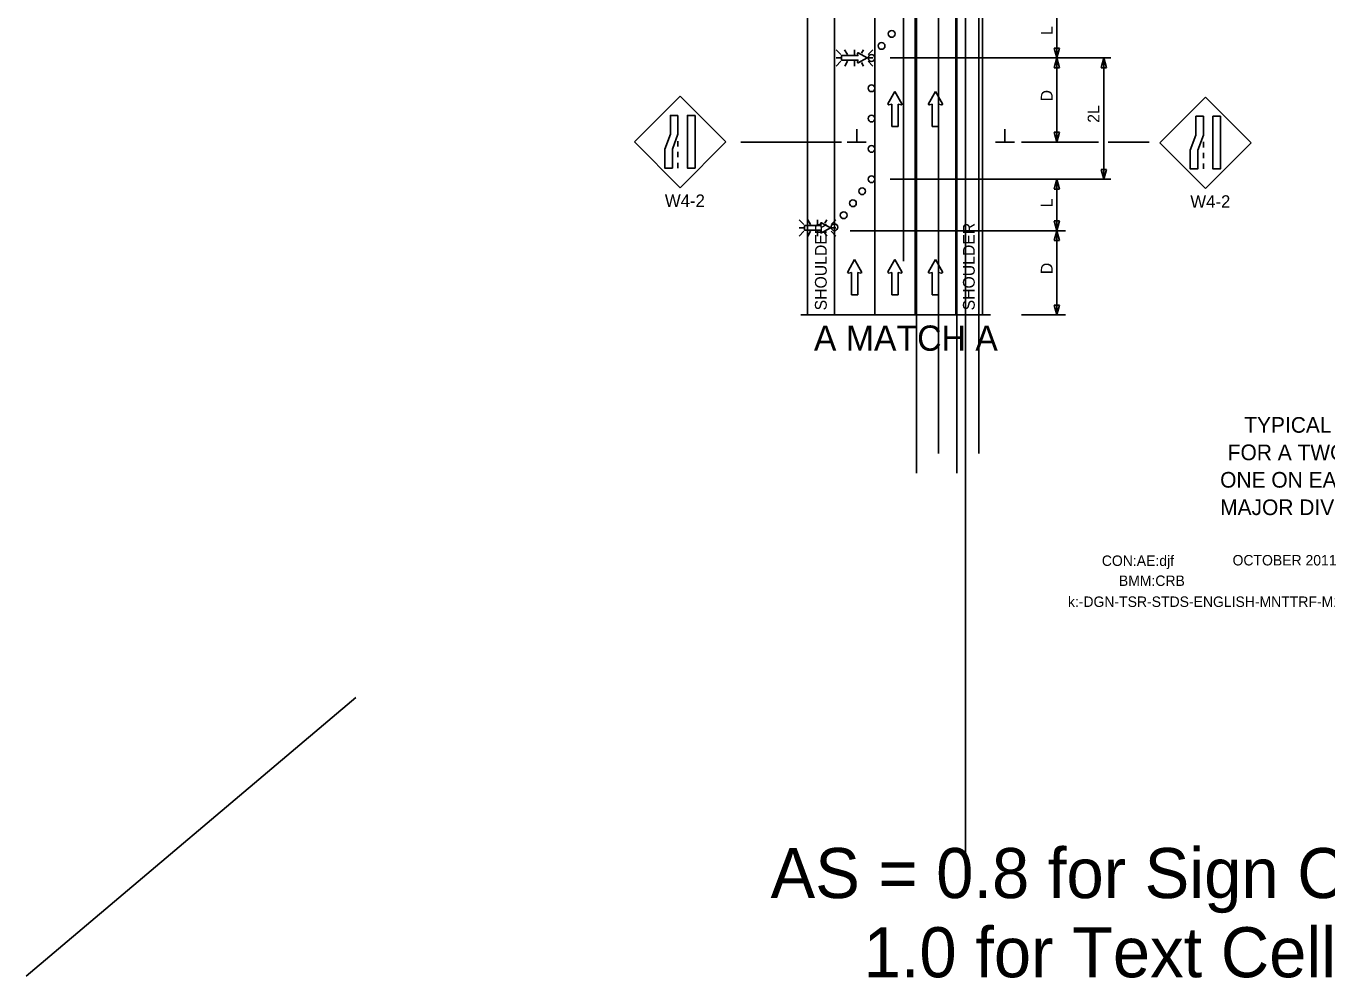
# Model space of a CAD drawing. Extents: x 16452 to 19508, y 5713 to 7079.
# Drawn here: x 16452 to 17224, y 5713 to 6279 of the extents above; entities that cross this region are included whole.
import ezdxf

# ---------------------------------------------------------------- set-up
doc = ezdxf.new("R2010")
doc.units = 0
for name, color, linetype in [('ALI_LEGAL_EX', 7, 'Continuous'), ('BORDER', 7, 'Continuous'), ('BORDER_SIGNAL_WO', 7, 'Continuous'), ('MT_SCRATCH_LEVEL_E', 7, 'Continuous'), ('PAVT_EDGE_EX', 7, 'Continuous'), ('TRAFFIC_SIGNS_PR', 7, 'Continuous'), ('TYPICAL_TEXT_DIMEN_PR', 7, 'Continuous')]:
    doc.layers.add(name, color=color, linetype=linetype)

msp = doc.modelspace()

# ---------------------------------------------------------------- linework, layer by layer
at = {"layer": 'ALI_LEGAL_EX'}
for p, q in [((16980.68, 6974.12), (16980.68, 6155.98)), ((17004.68, 6974.12), (17004.68, 6155.98)), ((16980.68, 6877.04), (16980.68, 6013.12)), ((17004.68, 6877.04), (17004.68, 6013.12)), ((16973.01, 6139.03), (16973.01, 6639.38)), ((16993.65, 6024.8), (16993.65, 6525.15)), ((17017.65, 6024.8), (17017.65, 6525.15)), ((16955.93, 6107.09), (16955.93, 6383.76)), ((16979.93, 6107.09), (16979.93, 6383.76)), ((17009.75, 5773.57), (17009.75, 6383.76))]:
    msp.add_line(p, q, dxfattribs=at)
for points in [[(16955.93, 6207.09), (16955.93, 6232.09)], [(16979.93, 6207.09), (16979.93, 6232.09)], [(16955.93, 6107.09), (16955.93, 6132.09)], [(16979.93, 6107.09), (16979.93, 6132.09)], [(16993.65, 6049.8), (16993.65, 6024.8)]]:
    msp.add_lwpolyline(points, dxfattribs=at)
at = {"layer": 'MT_SCRATCH_LEVEL_E'}
for p, q in [((16967.85, 6239.76), (16963.74, 6232.52)), ((16972, 6232.52), (16967.85, 6239.76)), ((16991.9, 6239.76), (16987.79, 6232.52)), ((16996.05, 6232.52), (16991.9, 6239.76)), ((16964.22, 6231.84), (16966, 6232.15)), ((16966, 6232.15), (16966, 6218.89)), ((16969.74, 6218.89), (16969.74, 6232.15)), ((16969.74, 6232.15), (16971.52, 6231.84)), ((16988.27, 6231.84), (16990.05, 6232.15)), ((16990.05, 6232.15), (16990.05, 6218.89)), ((16993.79, 6218.89), (16993.79, 6232.15)), ((16993.79, 6232.15), (16995.57, 6231.84)), ((16966, 6218.89), (16969.74, 6218.89)), ((16990.05, 6218.89), (16993.79, 6218.89)), ((16943.95, 6139.9), (16939.84, 6132.66)), ((16948.09, 6132.66), (16943.95, 6139.9)), ((16967.85, 6139.9), (16963.74, 6132.66)), ((16972, 6132.66), (16967.85, 6139.9)), ((16991.9, 6139.9), (16987.79, 6132.66)), ((16996.05, 6132.66), (16991.9, 6139.9)), ((16940.32, 6131.97), (16942.1, 6132.29)), ((16942.1, 6132.29), (16942.1, 6119.03)), ((16945.84, 6119.03), (16945.84, 6132.29)), ((16945.84, 6132.29), (16947.61, 6131.97)), ((16964.22, 6131.97), (16966, 6132.29)), ((16966, 6132.29), (16966, 6119.03)), ((16969.74, 6119.03), (16969.74, 6132.29)), ((16969.74, 6132.29), (16971.52, 6131.97)), ((16988.27, 6131.97), (16990.05, 6132.29)), ((16990.05, 6132.29), (16990.05, 6119.03)), ((16993.79, 6119.03), (16993.79, 6132.29)), ((16993.79, 6132.29), (16995.57, 6131.97)), ((16942.1, 6119.03), (16945.84, 6119.03)), ((16966, 6119.03), (16969.74, 6119.03)), ((16990.05, 6119.03), (16993.79, 6119.03))]:
    msp.add_line(p, q, dxfattribs=at)
for centre, start, end in [((16964.15, 6232.29), 150.42484, 279.96381), ((16971.59, 6232.29), 260.03619, 29.77312), ((16988.2, 6232.29), 150.42484, 279.96381), ((16995.64, 6232.29), 260.03619, 29.77312), ((16940.24, 6132.43), 150.42484, 279.96381), ((16947.68, 6132.43), 260.03619, 29.77312), ((16964.15, 6132.43), 150.42484, 279.96381), ((16971.59, 6132.43), 260.03619, 29.77312), ((16988.2, 6132.43), 150.42484, 279.96381), ((16995.64, 6132.43), 260.03619, 29.77312)]:
    msp.add_arc(centre, 0.463, start, end, dxfattribs=at)
at = {"layer": 'PAVT_EDGE_EX'}
for p, q in [((16915.93, 6383.76), (16915.93, 6107.09)), ((16931.93, 6383.76), (16931.93, 6107.09)), ((17003.93, 6383.76), (17003.93, 6107.09)), ((17019.93, 6383.76), (17019.93, 6107.09))]:
    msp.add_line(p, q, dxfattribs=at)
at = {"layer": 'TRAFFIC_SIGNS_PR'}
for p, q in [((16935.71, 6261.75), (16932.89, 6264.57)), ((16938, 6264.57), (16939.63, 6261.75)), ((16943.79, 6261.75), (16943.79, 6264.57)), ((16949.26, 6264.57), (16948.05, 6262.48)), ((16954.69, 6264.57), (16951.88, 6261.75)), ((16935.71, 6259.72), (16932.89, 6259.72)), ((16935.71, 6257.69), (16932.89, 6254.87)), ((16939.66, 6257.69), (16938.03, 6254.87)), ((16943.79, 6257.69), (16943.79, 6254.87)), ((16947.97, 6257.05), (16949.24, 6254.87)), ((16951.88, 6259.72), (16954.69, 6259.72)), ((16954.69, 6254.87), (16951.88, 6257.69)), ((16840.31, 6236.92), (16813.16, 6209.77)), ((16867.46, 6209.77), (16840.31, 6236.92)), ((17152.24, 6236.44), (17125.08, 6209.29)), ((17179.39, 6209.29), (17152.24, 6236.44)), ((16813.16, 6209.77), (16840.31, 6182.62)), ((16839.06, 6210.26), (16839.06, 6207.06)), ((16840.31, 6182.62), (16867.46, 6209.77)), ((17150.99, 6209.78), (17150.99, 6206.58)), ((16839.06, 6203.86), (16839.06, 6200.66)), ((17125.08, 6209.29), (17152.24, 6182.13)), ((17150.99, 6203.38), (17150.99, 6200.18)), ((17152.24, 6182.13), (17179.39, 6209.29)), ((16839.06, 6197.46), (16839.06, 6194.26)), ((17150.99, 6196.98), (17150.99, 6193.78)), ((16913.83, 6160.8), (16911.01, 6163.62)), ((16916.13, 6163.62), (16917.76, 6160.8)), ((16921.92, 6160.8), (16921.92, 6163.62)), ((16927.39, 6163.62), (16926.18, 6161.53)), ((16932.82, 6163.62), (16930, 6160.8)), ((16913.83, 6158.77), (16911.01, 6158.77)), ((16913.83, 6156.74), (16911.01, 6153.92)), ((16917.78, 6156.74), (16916.15, 6153.92)), ((16921.92, 6156.74), (16921.92, 6153.92)), ((16926.1, 6156.1), (16927.36, 6153.92)), ((16930, 6158.77), (16932.82, 6158.77)), ((16932.82, 6153.92), (16930, 6156.74))]:
    msp.add_line(p, q, dxfattribs=at)
for points in [[(16945.62, 6262.4), (16945.85, 6261.11), (16936.12, 6261.11), (16936.12, 6258.36), (16945.85, 6258.36), (16945.62, 6257.06)], [(16946.12, 6256.71), (16951.43, 6259.72), (16946.12, 6262.76)], [(16923.74, 6161.45), (16923.97, 6160.15), (16914.25, 6160.15), (16914.25, 6157.41), (16923.97, 6157.41), (16923.74, 6156.11)], [(16924.24, 6155.75), (16929.55, 6158.77), (16924.24, 6161.81)]]:
    msp.add_lwpolyline(points, dxfattribs=at)
for points in [[(16839.06, 6225.5), (16839.06, 6214.32), (16835.72, 6205.44), (16835.72, 6194.26), (16831.22, 6194.26), (16831.22, 6205.44), (16834.57, 6214.32), (16834.57, 6225.5)], [(16849.2, 6225.5), (16849.2, 6194.26), (16844.7, 6194.26), (16844.7, 6225.5)], [(17150.99, 6225.02), (17150.99, 6213.84), (17147.65, 6204.96), (17147.65, 6193.78), (17143.15, 6193.78), (17143.15, 6204.96), (17146.5, 6213.84), (17146.5, 6225.02)], [(17161.13, 6225.02), (17161.13, 6193.78), (17156.63, 6193.78), (17156.63, 6225.02)]]:
    msp.add_lwpolyline(points, close=True, dxfattribs=at)
for centre in [(16965.93, 6273.93), (16959.93, 6266.79), (16953.93, 6259.65), (16953.93, 6241.65), (16953.93, 6223.65), (16953.93, 6205.65), (16953.93, 6187.65), (16948.43, 6180.52), (16942.94, 6173.39), (16937.44, 6166.26), (16931.94, 6159.14)]:
    msp.add_circle(centre, 2, dxfattribs=at)
for centre, start, end in [((16945.95, 6262.46), 61.48329, 189.95933), ((16945.95, 6257.01), 170.73078, 298.89165), ((16924.08, 6161.51), 61.48329, 189.95933), ((16924.08, 6156.05), 170.73078, 298.89165)]:
    msp.add_arc(centre, 0.341, start, end, dxfattribs=at)
at = {"layer": 'TYPICAL_TEXT_DIMEN_PR'}
for p, q in [((17064.03, 6259.65), (17064.03, 6288.21)), ((17064.03, 6259.65), (17062.46, 6265.51)), ((17062.46, 6265.51), (17064.03, 6265.51)), ((17064.03, 6265.51), (17065.6, 6265.51)), ((17065.6, 6265.51), (17064.03, 6259.65)), ((17096.07, 6259.65), (16964.93, 6259.65)), ((17062.46, 6253.79), (17064.03, 6259.65)), ((17064.03, 6259.65), (17064.03, 6209.65)), ((17064.03, 6259.65), (17065.6, 6253.79)), ((17090.26, 6253.79), (17091.83, 6259.65)), ((17091.83, 6259.65), (17093.4, 6253.79)), ((17091.83, 6259.65), (17091.83, 6187.65)), ((17064.03, 6253.79), (17062.46, 6253.79)), ((17065.6, 6253.79), (17064.03, 6253.79)), ((17091.83, 6253.79), (17090.26, 6253.79)), ((17093.4, 6253.79), (17091.83, 6253.79)), ((16945.22, 6209.65), (16945.22, 6217.44)), ((17033.15, 6209.65), (17033.15, 6217.44)), ((16876.41, 6209.65), (16936.23, 6209.65)), ((16950.84, 6209.65), (16939.59, 6209.65)), ((17038.78, 6209.65), (17027.53, 6209.65)), ((17088.65, 6209.65), (17043.03, 6209.65)), ((17064.03, 6209.65), (17062.46, 6215.51)), ((17062.46, 6215.51), (17064.03, 6215.51)), ((17064.03, 6215.51), (17065.6, 6215.51)), ((17065.6, 6215.51), (17064.03, 6209.65)), ((17118.85, 6209.65), (17094.37, 6209.65)), ((16964.93, 6187.65), (17096.07, 6187.65)), ((17062.46, 6181.79), (17064.03, 6187.65)), ((17064.03, 6157.09), (17064.03, 6187.65)), ((17064.03, 6187.65), (17065.6, 6181.79)), ((17091.83, 6187.65), (17090.26, 6193.51)), ((17090.26, 6193.51), (17091.83, 6193.51)), ((17091.83, 6193.51), (17093.4, 6193.51)), ((17093.4, 6193.51), (17091.83, 6187.65)), ((17064.03, 6181.79), (17062.46, 6181.79)), ((17065.6, 6181.79), (17064.03, 6181.79)), ((16941.19, 6157.09), (17069.03, 6157.09)), ((17064.03, 6157.09), (17062.46, 6162.95)), ((17062.46, 6162.95), (17064.03, 6162.95)), ((17062.46, 6151.22), (17064.03, 6157.09)), ((17064.03, 6162.95), (17065.6, 6162.95)), ((17065.6, 6162.95), (17064.03, 6157.09)), ((17064.03, 6157.09), (17064.03, 6107.09)), ((17064.03, 6157.09), (17065.6, 6151.22)), ((17064.03, 6151.22), (17062.46, 6151.22)), ((17065.6, 6151.22), (17064.03, 6151.22)), ((17064.03, 6107.09), (17062.46, 6112.95)), ((17062.46, 6112.95), (17064.03, 6112.95)), ((17064.03, 6112.95), (17065.6, 6112.95)), ((17065.6, 6112.95), (17064.03, 6107.09)), ((16912, 6107.09), (17024.65, 6107.09)), ((17069.03, 6107.09), (17043.03, 6107.09)), ((16647.75, 5880), (16452.02, 5714.53))]:
    msp.add_line(p, q, dxfattribs=at)

# ---------------------------------------------------------------- texts
at = {"layer": 'BORDER'}
for s, p in [('TYPICAL TEMPORARY TRAFFIC CONTROL', (17175.21, 6037.14)), ('FOR A TWO-LANE CLOSURE ON A FREEWAY,', (17165.41, 6020.84)), ('ONE ON EACH SIDE OF A GORE AREA AT A ', (17160.92, 6004.54)), ('MAJOR DIVERGENCE USING A DOUBLE STEP ', (17160.92, 5988.24))]:
    msp.add_text(s, height=9.3, dxfattribs=at).set_placement(p)
at = {"layer": 'BORDER_SIGNAL_WO'}
for s, height, p in [('CON:AE:djf  ', 6.2, (17090.69, 5958.06)), ('    OCTOBER 2011    ', 6.2, (17159.08, 5958.34)), ('BMM:CRB   ', 6.2, (17100.81, 5946.17)), ('k:-DGN-TSR-STDS-ENGLISH-MNTTRF-M1550a.dgn      ', 6.2, (17070.55, 5933.71)), ('AS = 0.8 for Sign Cells', 29.7271, (16894.01, 5760.83)), ('     1.0 for Text Cells', 29.7271, (16894.01, 5713.82))]:
    msp.add_text(s, height=height, dxfattribs=at).set_placement(p)
at = {"layer": 'TRAFFIC_SIGNS_PR'}
for p in [(16831.27, 6171.18), (17143.2, 6170.69)]:
    msp.add_text('W4-2', height=7.44, dxfattribs=at).set_placement(p)
at = {"layer": 'TYPICAL_TEXT_DIMEN_PR'}
for s, p in [('L', (17061.56, 6273.29)), ('D', (17061.47, 6233.87)), ('2L', (17089.28, 6221.15)), ('L', (17061.47, 6170.94)), ('SHOULDER', (16927.37, 6109.79)), ('SHOULDER', (17015.23, 6109.79)), ('D', (17061.47, 6131.3))]:
    msp.add_text(s, height=7, rotation=90, dxfattribs=at).set_placement(p)
msp.add_text('A MATCH A', height=15, dxfattribs=at).set_placement((16919.74, 6085.81))

doc.saveas('drawing.dxf')
